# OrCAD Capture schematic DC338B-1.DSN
size Custom; title: ACTIVE RC LOWPASS/BANDPASS FILTER; rev: 1; company: TM
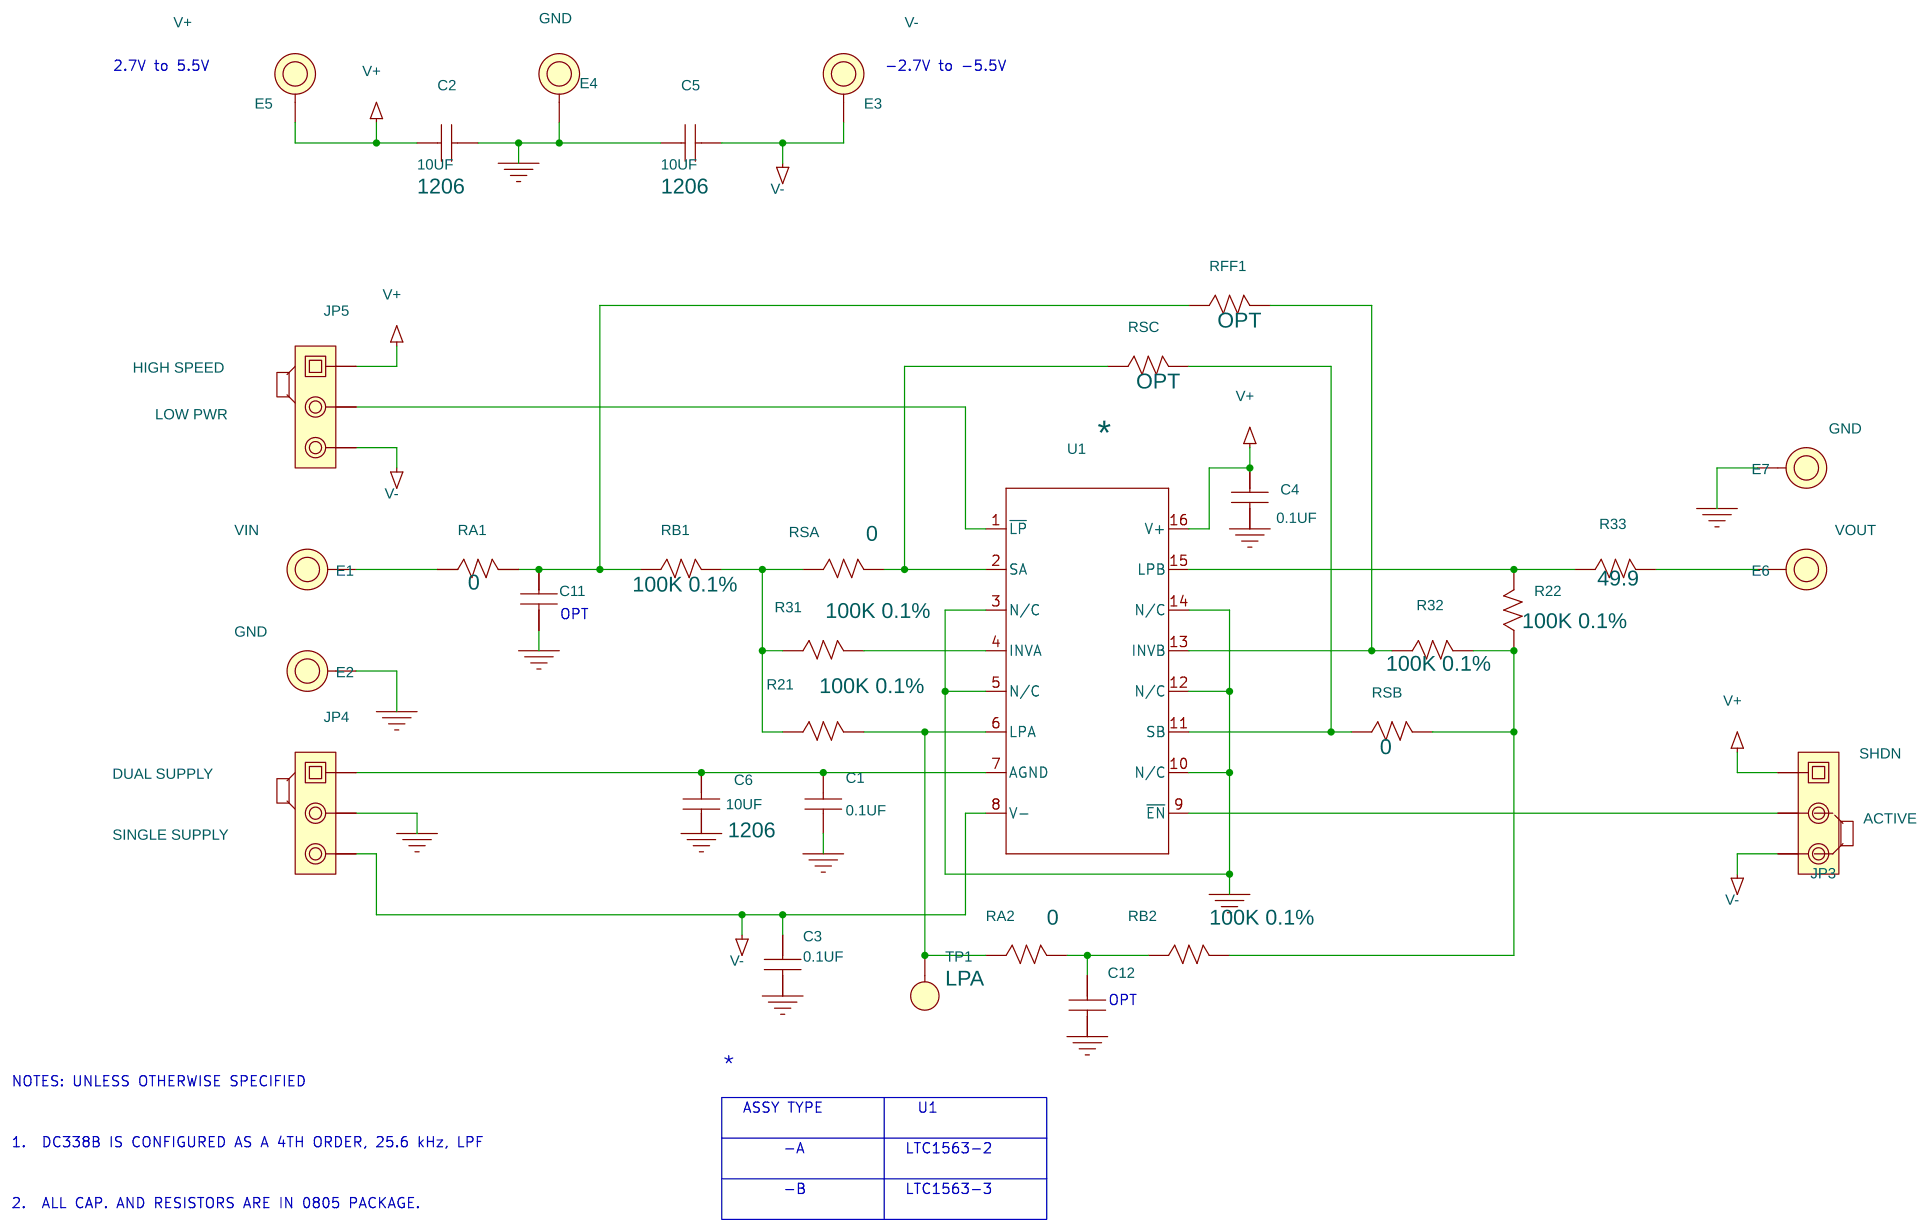
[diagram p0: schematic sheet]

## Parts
C1  0.1UF  [0805S]
C2  10UF  [1206]
C3  0.1UF  [0805S]
C4  0.1UF  [0805S]
C5  10UF  [1206]
C6  10UF  [1206]
C11  CAP NP  [0805S]
C12  CAP NP  [0805S]
E1  VIN  [MILLMAX2501]
E2  GND  [MILLMAX2501]
E3  V-  [MILLMAX2501]
E4  GND  [MILLMAX2501]
E5  V+  [MILLMAX2501]
E6  VOUT  [MILLMAX2501]
E7  GND  [MILLMAX2501]
JP3  3 Pins 2mm Ctrs.  [HDR-3X1-2MM]
JP4  3 Pins 2mm Ctrs.  [HDR-3X1-2MM]
JP5  3 Pins 2mm Ctrs.  [HDR-3X1-2MM]
R21  100K 0.1%  [0805S]
R22  100K 0.1%  [0805S]
R31  100K 0.1%  [0805S]
R32  100K 0.1%  [0805S]
R33  49.9  [0805S]
RA1  0  [0805S]
RA2  0  [0805S]
RB1  100K 0.1%  [0805S]
RB2  100K 0.1%  [0805S]
RFF1  OPT  [0805S]
RSA  0  [0805S]
RSB  0  [0805S]
RSC  OPT  [0805S]
TP1  LPA  [PAD150-094]
U1  *  [SSOP16GN]
XJP1  2mm Ctrs.
XJP2  2mm Ctrs.
XJP3  2mm Ctrs.

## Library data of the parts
C1-C6 C11 C12 = CAP_NP
E1-E7 = CON_KEY_575-4_2: 4th Part Field: ??//??
JP3 = Samtec_TMM-103-02-L-S_8: HEADER, 3 PIN; 11th Part Field: SHDN; 12th Part Field: ACTIVE; 9th Part Field: VLOGIC; Part Number: SAMTEC TMM-103-02-L-S
JP4 = Samtec_TMM-103-02-L-S_8: HEADER, 3 PIN; 11th Part Field: SINGLE SUPPLY; 12th Part Field: DUAL SUPPLY; 9th Part Field: VLOGIC; Part Number: SAMTEC TMM-103-02-L-S
JP5 = Samtec_TMM-103-02-L-S_8: HEADER, 3 PIN; 11th Part Field: HIGH SPEED; 12th Part Field: LOW PWR; 9th Part Field: VLOGIC; Part Number: SAMTEC TMM-103-02-L-S
R21 R22 R31-R33 RA1 RA2 RB1 RB2 RFF1 RSA RSB RSC = R-SMALL
TP1 = E
U1 = LTC1563-16P_0
XJP1-XJP3 = CommconCCIJ2MM-138G

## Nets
GND: C1.1 C2.2 C3.2 C4.2 C5.1 C6.1 C11.2 C12.2 E2.1 E4.1 E7.1 JP4.2 U1.3(N/C) U1.5(N/C) U1.10(N/C) U1.12(N/C) U1.14(N/C)
V+: C2.1 C4.1 E5.1 JP3.1 JP5.1 U1.16(V+)
V-: C3.1 C5.2 E3.1 JP3.3 JP4.3 JP5.3 U1.8(V-)
N16983296: R21.1 R31.1 RB1.2 RSA.1
N16983302: R21.2 RA2.1 TP1.1(A) U1.6(LPA)
N16983390: JP5.2 U1.1(~{LP})
N16983439: R31.2 U1.4(INVA)
N16983471: C11.1 RA1.2 RB1.1 RFF1.1
N16983496: E1.1 RA1.1
N16983605: C12.1 RA2.2 RB2.1
N16983672: R22.2 R33.1 U1.15(LPB)
N16983674: R22.1 R32.2 RB2.2 RSB.2
N16983676: R32.1 RFF1.2 U1.13(INVB)
N16983678: JP3.2 U1.9(~{EN})
N16983739: C1.2 C6.2 JP4.1 U1.7(AGND)
N16997385: RSA.2 RSC.1 U1.2(SA)
N17002042: E6.1 R33.2
N17004283: RSB.1 RSC.2 U1.11(SB)

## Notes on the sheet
- 2.7V to 5.5V
- -2.7V to -5.5V
- OPT
- OPT
- *
- NOTES: UNLESS OTHERWISE SPECIFIED
- ASSY TYPE
- U1
- 1.  DC338B IS CONFIGURED AS A 4TH ORDER, 25.6 kHz, LPF
- -A
- LTC1563-2
- -B
- LTC1563-3
- 2.  ALL CAP. AND RESISTORS ARE IN 0805 PACKAGE.
